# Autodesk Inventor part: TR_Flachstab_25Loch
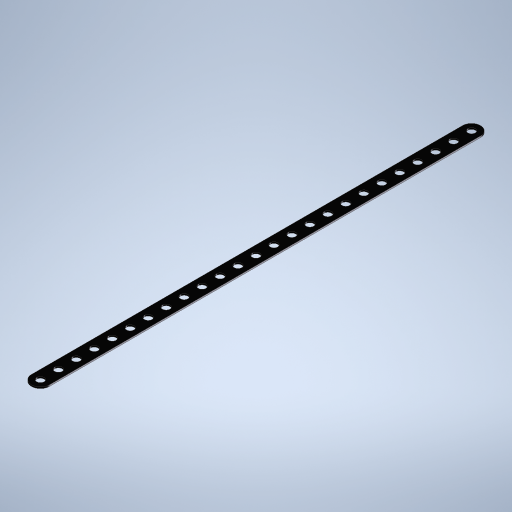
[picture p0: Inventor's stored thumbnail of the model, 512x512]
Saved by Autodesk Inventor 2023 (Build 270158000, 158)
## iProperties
Created: 2023-11
Part Number: TR_Flachstab_25Loch
Material: Edelstahl
Document SubType Name: Modeling
Designer: Admin
Density: 8 g/cm^3
Appearance: Halbpoliert
Author: Admin
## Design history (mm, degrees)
sketch "Skizze1"
  geometry: L1 (0, 120)-(0, -120); L2 (-5, 120)-(-5, -120); L3 (5, -120)-(5, 120); A1 r 5 centre (0, 120) between (5, 120) and (-5, 120); A2 r 5 centre (0, -120) between (-5, -120) and (5, -120); 3 further points
  constraints: 8 end point, 4 point on circle, 4 tangent, 2 centre point, 2 midpoint, 1 horizontal alignment, 1 parallel, 1 vertical, 1 vertical alignment
  dimensions: "d0" = 240 distance of L1.start L1.end (computed from Loch, Einheitsmaß); "d1" = 5 radius of A1 (= 0.5 x Einheitsmaß)
extrude "Extrusion1" new body sketch "Skizze1" distance "d5" = 0.8 (= Dicke); taper "d6" = 0 deg
sketch "Skizze2"
  geometry: C1 r 2.075 at (0, 120); A1 r 5 centre (0, 120) between (5, 120) and (-5, 120) reference; 1 further point
  constraints: 1 centre point, 1 coincident
  dimensions: "d7" = 4.15 diameter of C1 (= 2 x Radius)
extrude "Extrusion2" cut sketch "Skizze2" stored distance "d8" = 10; taper "d9" = 0 deg
node "Volumenkörper1"
pattern_linear "Rechteckige Anordnung1" dims "d12" = 10 (= Einheitsmaß)
other parameters: "Einheitsmaß" = 10 [user parameter; used in 3 equation terms], "Radius" = 2.075 [user parameter; used in 1 equation term], "Fasen" = 0.5 [user parameter], "Dicke" = 0.8 [user parameter; used in 1 equation term]
